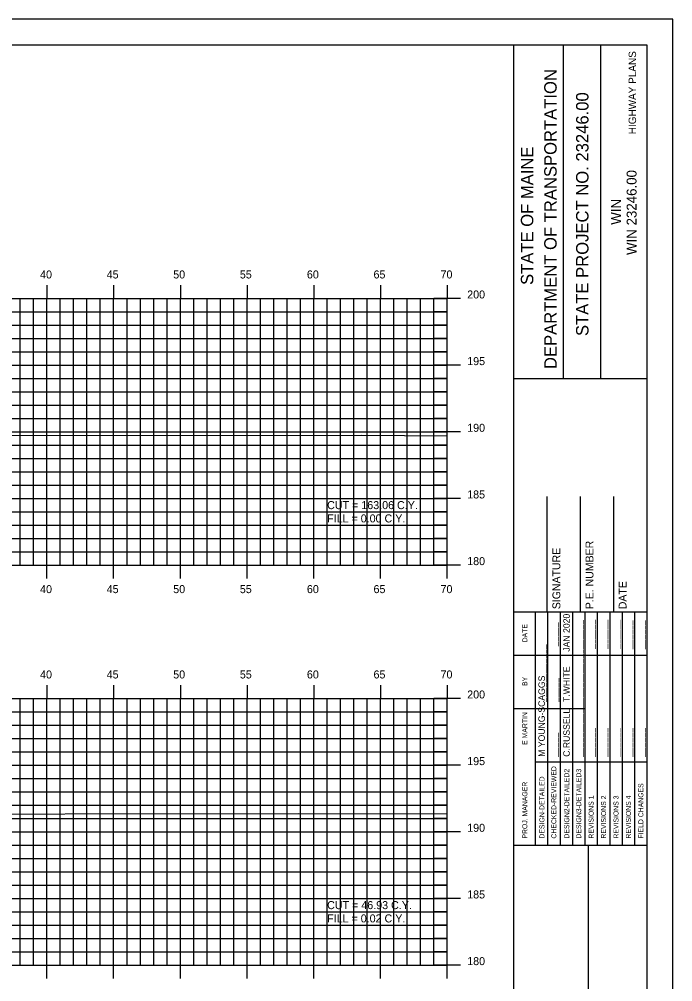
# Model space of a CAD drawing. Extents: x 1139207 to 1139377, y 608981 to 609091.
# Drawn here: x 1139327.6 to 1139376.6, y 609019.1 to 609091.3 of the extents above; entities that cross this region are included whole.
import ezdxf

# ---------------------------------------------------------------- set-up
doc = ezdxf.new("R2010")
doc.units = 0
for name, color, linetype in [('BORDER', 7, 'Continuous'), ('D_Text_Standard', 7, 'Continuous'), ('H_V ANNOTATION', 7, 'Continuous'), ('HIGHWAY_TITLE', 7, 'Continuous'), ('MAJOR', 7, 'Continuous'), ('MINOR', 7, 'Continuous'), ('PLOT BOUNDARY', 7, 'Continuous'), ('S_Roadway_Centerline', 7, 'Continuous')]:
    doc.layers.add(name, color=color, linetype=linetype)

msp = doc.modelspace()

# ---------------------------------------------------------------- linework, layer by layer
at = {"layer": 'BORDER'}
for p, q in [((1139364.705, 608984.335), (1139364.705, 609089.335)), ((1139368.434, 609064.332), (1139368.434, 609089.332)), ((1139371.229, 609064.332), (1139371.229, 609089.332)), ((1139364.706, 609064.329), (1139374.705, 609064.329)), ((1139367.205, 609046.838), (1139367.205, 609055.485)), ((1139369.705, 609046.838), (1139369.705, 609055.485)), ((1139372.205, 609046.838), (1139372.205, 609055.485)), ((1139364.705, 609046.838), (1139374.705, 609046.838)), ((1139364.705, 609029.338), (1139374.705, 609029.338)), ((1139370.296, 608994.338), (1139370.296, 609029.338))]:
    msp.add_line(p, q, dxfattribs=at)
msp.add_lwpolyline([(1139214.705, 608984.335), (1139374.705, 608984.335), (1139374.705, 609089.335), (1139214.705, 609089.335)], close=True, dxfattribs=at)
for points in [[(1139366.32, 609043.588), (1139366.32, 609046.838)], [(1139367.253, 609029.341), (1139367.253, 609046.838)], [(1139368.185, 609046.838), (1139368.185, 609029.341)], [(1139369.116, 609029.341), (1139369.116, 609046.838)], [(1139370.048, 609029.341), (1139370.048, 609046.838)], [(1139370.98, 609029.341), (1139370.98, 609046.838)], [(1139371.911, 609029.341), (1139371.911, 609046.838)], [(1139372.843, 609029.341), (1139372.843, 609046.838)], [(1139373.775, 609029.341), (1139373.775, 609046.838)], [(1139366.321, 609029.341), (1139366.321, 609046.132)], [(1139364.705, 609043.588), (1139374.705, 609043.588)], [(1139364.705, 609039.588), (1139366.321, 609039.588)], [(1139366.32, 609039.588), (1139370.047, 609039.588)], [(1139366.32, 609035.588), (1139374.705, 609035.588)]]:
    msp.add_lwpolyline(points, dxfattribs=at)
at = {"layer": 'MAJOR'}
for p, q in [((1139329.705, 609071.337), (1139329.705, 609070.335)), ((1139334.705, 609071.337), (1139334.705, 609070.335)), ((1139339.705, 609071.337), (1139339.705, 609070.335)), ((1139344.705, 609071.337), (1139344.705, 609070.335)), ((1139349.705, 609071.337), (1139349.705, 609070.335)), ((1139354.705, 609071.337), (1139354.705, 609070.335)), ((1139359.705, 609071.337), (1139359.705, 609070.335)), ((1139219.705, 609070.335), (1139359.705, 609070.335)), ((1139219.705, 609070.335), (1139359.705, 609070.335)), ((1139329.705, 609050.335), (1139329.705, 609070.335)), ((1139334.705, 609050.335), (1139334.705, 609070.335)), ((1139339.705, 609050.335), (1139339.705, 609070.335)), ((1139344.705, 609050.335), (1139344.705, 609070.335)), ((1139349.705, 609050.335), (1139349.705, 609070.335)), ((1139354.705, 609050.335), (1139354.705, 609070.335)), ((1139360.707, 609070.335), (1139358.703, 609070.335)), ((1139359.705, 609050.335), (1139359.705, 609070.335)), ((1139359.705, 609050.335), (1139359.705, 609070.335)), ((1139219.705, 609065.335), (1139359.705, 609065.335)), ((1139360.707, 609065.335), (1139358.703, 609065.335)), ((1139219.705, 609060.335), (1139359.705, 609060.335)), ((1139360.707, 609060.335), (1139358.703, 609060.335)), ((1139219.705, 609055.335), (1139359.705, 609055.335)), ((1139360.707, 609055.335), (1139358.703, 609055.335)), ((1139219.705, 609050.335), (1139359.705, 609050.335)), ((1139219.705, 609050.335), (1139359.705, 609050.335)), ((1139329.705, 609049.333), (1139329.705, 609050.335)), ((1139334.705, 609049.333), (1139334.705, 609050.335)), ((1139339.705, 609049.333), (1139339.705, 609050.335)), ((1139344.705, 609049.333), (1139344.705, 609050.335)), ((1139349.705, 609049.333), (1139349.705, 609050.335)), ((1139354.705, 609049.333), (1139354.705, 609050.335)), ((1139360.707, 609050.335), (1139358.703, 609050.335)), ((1139359.705, 609049.333), (1139359.705, 609050.335)), ((1139329.705, 609041.337), (1139329.705, 609040.335)), ((1139334.705, 609041.337), (1139334.705, 609040.335)), ((1139339.705, 609041.337), (1139339.705, 609040.335)), ((1139344.705, 609041.337), (1139344.705, 609040.335)), ((1139349.705, 609041.337), (1139349.705, 609040.335)), ((1139354.705, 609041.337), (1139354.705, 609040.335)), ((1139359.705, 609041.337), (1139359.705, 609040.335)), ((1139219.705, 609040.335), (1139359.705, 609040.335)), ((1139219.705, 609040.335), (1139359.705, 609040.335)), ((1139329.705, 609020.335), (1139329.705, 609040.335)), ((1139334.705, 609020.335), (1139334.705, 609040.335)), ((1139339.705, 609020.335), (1139339.705, 609040.335)), ((1139344.705, 609020.335), (1139344.705, 609040.335)), ((1139349.705, 609020.335), (1139349.705, 609040.335)), ((1139354.705, 609020.335), (1139354.705, 609040.335)), ((1139360.707, 609040.335), (1139358.703, 609040.335)), ((1139359.705, 609020.335), (1139359.705, 609040.335)), ((1139359.705, 609020.335), (1139359.705, 609040.335)), ((1139219.705, 609035.335), (1139359.705, 609035.335)), ((1139360.707, 609035.335), (1139358.703, 609035.335)), ((1139219.705, 609030.335), (1139359.705, 609030.335)), ((1139360.707, 609030.335), (1139358.703, 609030.335)), ((1139219.705, 609025.335), (1139359.705, 609025.335)), ((1139360.707, 609025.335), (1139358.703, 609025.335)), ((1139219.705, 609020.335), (1139359.705, 609020.335)), ((1139219.705, 609020.335), (1139359.705, 609020.335)), ((1139329.705, 609019.333), (1139329.705, 609020.335)), ((1139334.705, 609019.333), (1139334.705, 609020.335)), ((1139339.705, 609019.333), (1139339.705, 609020.335)), ((1139344.705, 609019.333), (1139344.705, 609020.335)), ((1139349.705, 609019.333), (1139349.705, 609020.335)), ((1139354.705, 609019.333), (1139354.705, 609020.335)), ((1139360.707, 609020.335), (1139358.703, 609020.335)), ((1139359.705, 609019.333), (1139359.705, 609020.335))]:
    msp.add_line(p, q, dxfattribs=at)
at = {"layer": 'MINOR'}
for p, q in [((1139327.705, 609050.335), (1139327.705, 609070.335)), ((1139328.705, 609050.335), (1139328.705, 609070.335)), ((1139330.705, 609050.335), (1139330.705, 609070.335)), ((1139331.705, 609050.335), (1139331.705, 609070.335)), ((1139332.705, 609050.335), (1139332.705, 609070.335)), ((1139333.705, 609050.335), (1139333.705, 609070.335)), ((1139335.705, 609050.335), (1139335.705, 609070.335)), ((1139336.705, 609050.335), (1139336.705, 609070.335)), ((1139337.705, 609050.335), (1139337.705, 609070.335)), ((1139338.705, 609050.335), (1139338.705, 609070.335)), ((1139340.705, 609050.335), (1139340.705, 609070.335)), ((1139341.705, 609050.335), (1139341.705, 609070.335)), ((1139342.705, 609050.335), (1139342.705, 609070.335)), ((1139343.705, 609050.335), (1139343.705, 609070.335)), ((1139345.705, 609050.335), (1139345.705, 609070.335)), ((1139346.705, 609050.335), (1139346.705, 609070.335)), ((1139347.705, 609050.335), (1139347.705, 609070.335)), ((1139348.705, 609050.335), (1139348.705, 609070.335)), ((1139350.705, 609050.335), (1139350.705, 609070.335)), ((1139351.705, 609050.335), (1139351.705, 609070.335)), ((1139352.705, 609050.335), (1139352.705, 609070.335)), ((1139353.705, 609050.335), (1139353.705, 609070.335)), ((1139355.705, 609050.335), (1139355.705, 609070.335)), ((1139356.705, 609050.335), (1139356.705, 609070.335)), ((1139357.705, 609050.335), (1139357.705, 609070.335)), ((1139358.705, 609050.335), (1139358.705, 609070.335)), ((1139219.705, 609069.335), (1139359.705, 609069.335)), ((1139359.705, 609069.335), (1139358.703, 609069.335)), ((1139219.705, 609068.335), (1139359.705, 609068.335)), ((1139359.705, 609068.335), (1139358.703, 609068.335)), ((1139219.705, 609067.335), (1139359.705, 609067.335)), ((1139359.705, 609067.335), (1139358.703, 609067.335)), ((1139219.705, 609066.335), (1139359.705, 609066.335)), ((1139359.705, 609066.335), (1139358.703, 609066.335)), ((1139219.705, 609064.335), (1139359.705, 609064.335)), ((1139359.705, 609064.335), (1139358.703, 609064.335)), ((1139219.705, 609063.335), (1139359.705, 609063.335)), ((1139359.705, 609063.335), (1139358.703, 609063.335)), ((1139219.705, 609062.335), (1139359.705, 609062.335)), ((1139359.705, 609062.335), (1139358.703, 609062.335)), ((1139219.705, 609061.335), (1139359.705, 609061.335)), ((1139359.705, 609061.335), (1139358.703, 609061.335)), ((1139219.705, 609059.335), (1139359.705, 609059.335)), ((1139359.705, 609059.335), (1139358.703, 609059.335)), ((1139219.705, 609058.335), (1139359.705, 609058.335)), ((1139359.705, 609058.335), (1139358.703, 609058.335)), ((1139219.705, 609057.335), (1139359.705, 609057.335)), ((1139359.705, 609057.335), (1139358.703, 609057.335)), ((1139219.705, 609056.335), (1139359.705, 609056.335)), ((1139359.705, 609056.335), (1139358.703, 609056.335)), ((1139219.705, 609054.335), (1139359.705, 609054.335)), ((1139359.705, 609054.335), (1139358.703, 609054.335)), ((1139219.705, 609053.335), (1139359.705, 609053.335)), ((1139359.705, 609053.335), (1139358.703, 609053.335)), ((1139219.705, 609052.335), (1139359.705, 609052.335)), ((1139359.705, 609052.335), (1139358.703, 609052.335)), ((1139219.705, 609051.335), (1139359.705, 609051.335)), ((1139359.705, 609051.335), (1139358.703, 609051.335)), ((1139327.705, 609020.335), (1139327.705, 609040.335)), ((1139328.705, 609020.335), (1139328.705, 609040.335)), ((1139330.705, 609020.335), (1139330.705, 609040.335)), ((1139331.705, 609020.335), (1139331.705, 609040.335)), ((1139332.705, 609020.335), (1139332.705, 609040.335)), ((1139333.705, 609020.335), (1139333.705, 609040.335)), ((1139335.705, 609020.335), (1139335.705, 609040.335)), ((1139336.705, 609020.335), (1139336.705, 609040.335)), ((1139337.705, 609020.335), (1139337.705, 609040.335)), ((1139338.705, 609020.335), (1139338.705, 609040.335)), ((1139340.705, 609020.335), (1139340.705, 609040.335)), ((1139341.705, 609020.335), (1139341.705, 609040.335)), ((1139342.705, 609020.335), (1139342.705, 609040.335)), ((1139343.705, 609020.335), (1139343.705, 609040.335)), ((1139345.705, 609020.335), (1139345.705, 609040.335)), ((1139346.705, 609020.335), (1139346.705, 609040.335)), ((1139347.705, 609020.335), (1139347.705, 609040.335)), ((1139348.705, 609020.335), (1139348.705, 609040.335)), ((1139350.705, 609020.335), (1139350.705, 609040.335)), ((1139351.705, 609020.335), (1139351.705, 609040.335)), ((1139352.705, 609020.335), (1139352.705, 609040.335)), ((1139353.705, 609020.335), (1139353.705, 609040.335)), ((1139355.705, 609020.335), (1139355.705, 609040.335)), ((1139356.705, 609020.335), (1139356.705, 609040.335)), ((1139357.705, 609020.335), (1139357.705, 609040.335)), ((1139358.705, 609020.335), (1139358.705, 609040.335)), ((1139219.705, 609039.335), (1139359.705, 609039.335)), ((1139359.705, 609039.335), (1139358.703, 609039.335)), ((1139219.705, 609038.335), (1139359.705, 609038.335)), ((1139359.705, 609038.335), (1139358.703, 609038.335)), ((1139219.705, 609037.335), (1139359.705, 609037.335)), ((1139359.705, 609037.335), (1139358.703, 609037.335)), ((1139219.705, 609036.335), (1139359.705, 609036.335)), ((1139359.705, 609036.335), (1139358.703, 609036.335)), ((1139219.705, 609034.335), (1139359.705, 609034.335)), ((1139359.705, 609034.335), (1139358.703, 609034.335)), ((1139219.705, 609033.335), (1139359.705, 609033.335)), ((1139359.705, 609033.335), (1139358.703, 609033.335)), ((1139219.705, 609032.335), (1139359.705, 609032.335)), ((1139359.705, 609032.335), (1139358.703, 609032.335)), ((1139219.705, 609031.335), (1139359.705, 609031.335)), ((1139359.705, 609031.335), (1139358.703, 609031.335)), ((1139219.705, 609029.335), (1139359.705, 609029.335)), ((1139359.705, 609029.335), (1139358.703, 609029.335)), ((1139219.705, 609028.335), (1139359.705, 609028.335)), ((1139359.705, 609028.335), (1139358.703, 609028.335)), ((1139219.705, 609027.335), (1139359.705, 609027.335)), ((1139359.705, 609027.335), (1139358.703, 609027.335)), ((1139219.705, 609026.335), (1139359.705, 609026.335)), ((1139359.705, 609026.335), (1139358.703, 609026.335)), ((1139219.705, 609024.335), (1139359.705, 609024.335)), ((1139359.705, 609024.335), (1139358.703, 609024.335)), ((1139219.705, 609023.335), (1139359.705, 609023.335)), ((1139359.705, 609023.335), (1139358.703, 609023.335)), ((1139219.705, 609022.335), (1139359.705, 609022.335)), ((1139359.705, 609022.335), (1139358.703, 609022.335)), ((1139219.705, 609021.335), (1139359.705, 609021.335)), ((1139359.705, 609021.335), (1139358.703, 609021.335))]:
    msp.add_line(p, q, dxfattribs=at)
at = {"layer": 'PLOT BOUNDARY'}
msp.add_lwpolyline([(1139206.612, 608981.276), (1139376.612, 608981.276), (1139376.612, 609091.276), (1139206.612, 609091.276)], close=True, dxfattribs=at)
at = {"layer": 'S_Roadway_Centerline'}
for points in [[(1139231.693, 609064.2), (1139235.188, 609064.142), (1139236.871, 609064.001), (1139239.489, 609063.871), (1139241.838, 609063.755), (1139250.238, 609063.378), (1139264.143, 609062.648), (1139264.256, 609062.641), (1139272.57, 609061.866), (1139275.873, 609061.633), (1139276.892, 609061.652), (1139282.291, 609061.733), (1139287.04, 609061.756), (1139292.681, 609061.794), (1139292.709, 609061.781), (1139297.486, 609061.69), (1139303.847, 609061.636), (1139305.717, 609061.239), (1139307.637, 609060.852), (1139309.089, 609060.674), (1139312.659, 609060.053), (1139353.311, 609060.081), (1139359.705, 609060.02)], [(1139268.743, 609032.962), (1139276.277, 609032.574), (1139276.277, 609032.574), (1139276.277, 609032.574), (1139278.743, 609032.693), (1139281.778, 609032.801), (1139285.759, 609032.805), (1139292.65, 609032.921), (1139292.728, 609033.025), (1139295.683, 609032.864), (1139303.307, 609032.796), (1139307.64, 609032.149), (1139307.746, 609032.136), (1139307.838, 609032.108), (1139308.052, 609032.088), (1139311.845, 609031.608), (1139313.562, 609031.651), (1139348.525, 609031.696), (1139359.705, 609031.676)]]:
    msp.add_lwpolyline(points, dxfattribs=at)

# ---------------------------------------------------------------- texts
at = {"layer": 'BORDER'}
for s, height, p in [('DEPARTMENT OF TRANSPORTATION', 0.93176, (1139367.912, 609065.041)), ('STATE PROJECT NO. 23246.00', 0.93176, (1139370.297, 609067.517)), ('STATE OF MAINE', 0.93176, (1139366.161, 609071.347)), ('WIN 23246.00', 0.74527, (1139373.901, 609073.596)), ('WIN', 0.7453, (1139372.742, 609075.865)), ('SIGNATURE', 0.5906, (1139368.186, 609047.03)), ('P.E. NUMBER', 0.59055, (1139370.666, 609047.03)), ('DATE', 0.5906, (1139373.147, 609047.03)), ('JAN 2020', 0.4845, (1139368.892, 609043.843)), ('DATE', 0.3714, (1139365.71, 609044.544)), ('_____', 0.4845, (1139367.923, 609044.243)), ('______', 0.4845, (1139369.786, 609044.063)), ('______', 0.4845, (1139370.718, 609044.065)), ('______', 0.4845, (1139371.65, 609044.067)), ('______', 0.4845, (1139372.581, 609044.067)), ('______', 0.4845, (1139373.513, 609044.036)), ('______', 0.4845, (1139374.445, 609044.036)), ('____________', 0.48455, (1139367.028, 609040.073)), ('____________', 0.48455, (1139369.786, 609040.073)), ('T.WHITE', 0.4845, (1139368.892, 609040.073)), ('BY', 0.3714, (1139365.71, 609041.273)), ('M YOUNG-SCAGGS', 0.48455, (1139367.028, 609035.961)), ('_____', 0.4845, (1139367.96, 609040.073)), ('____________', 0.48455, (1139369.786, 609035.961)), ('C.RUSSELL', 0.4845, (1139368.892, 609035.961)), ('E MARTIN', 0.3727, (1139365.71, 609036.855)), ('_____', 0.4845, (1139367.923, 609035.961)), ('______', 0.4845, (1139370.718, 609035.961)), ('______', 0.4845, (1139371.65, 609035.961)), ('______', 0.4845, (1139372.581, 609035.961)), ('______', 0.4845, (1139373.513, 609035.961)), ('______', 0.4845, (1139374.445, 609035.961)), ('CHECKED-REVIEWED', 0.37275, (1139367.886, 609029.826)), ('DESIGN2-DETAILED2', 0.37275, (1139368.855, 609029.826)), ('DESIGN3-DETAILED3', 0.37275, (1139369.75, 609029.826)), ('DESIGN-DETAILED', 0.37275, (1139366.992, 609029.826)), ('PROJ. MANAGER', 0.37275, (1139365.71, 609029.826)), ('FIELD CHANGES', 0.37275, (1139374.408, 609029.826)), ('REVISIONS 1', 0.37275, (1139370.681, 609029.826)), ('REVISIONS 2', 0.37275, (1139371.613, 609029.826)), ('REVISIONS 3', 0.37275, (1139372.545, 609029.826)), ('REVISIONS 4', 0.37275, (1139373.477, 609029.826))]:
    msp.add_text(s, height=height, rotation=90, dxfattribs=at).set_placement(p)
at = {"layer": 'D_Text_Standard'}
for s, p in [('CUT = 163.06 C.Y.', (1139350.705, 609054.535)), ('FILL = 0.00 C.Y.', (1139350.705, 609053.539)), ('CUT = 46.93 C.Y.', (1139350.705, 609024.535)), ('FILL = 0.02 C.Y.', (1139350.705, 609023.539))]:
    msp.add_text(s, height=0.6, dxfattribs=at).set_placement(p)
at = {"layer": 'H_V ANNOTATION'}
for s, p in [('40', (1139329.191, 609071.835)), ('45', (1139334.183, 609071.835)), ('50', (1139339.17, 609071.835)), ('55', (1139344.162, 609071.835)), ('60', (1139349.191, 609071.835)), ('65', (1139354.183, 609071.835)), ('70', (1139359.207, 609071.835)), ('200', (1139361.205, 609070.335)), ('195', (1139361.205, 609065.335)), ('190', (1139361.205, 609060.335)), ('185', (1139361.205, 609055.335)), ('180', (1139361.205, 609050.335)), ('40', (1139329.191, 609048.235)), ('45', (1139334.183, 609048.235)), ('50', (1139339.17, 609048.235)), ('55', (1139344.162, 609048.235)), ('60', (1139349.191, 609048.235)), ('65', (1139354.183, 609048.235)), ('70', (1139359.207, 609048.235)), ('40', (1139329.191, 609041.835)), ('45', (1139334.183, 609041.835)), ('50', (1139339.17, 609041.835)), ('55', (1139344.162, 609041.835)), ('60', (1139349.191, 609041.835)), ('65', (1139354.183, 609041.835)), ('70', (1139359.207, 609041.835)), ('200', (1139361.205, 609040.335)), ('195', (1139361.205, 609035.335)), ('190', (1139361.205, 609030.335)), ('185', (1139361.205, 609025.335)), ('180', (1139361.205, 609020.335))]:
    msp.add_text(s, height=0.6, dxfattribs=at).set_placement(p)
at = {"layer": 'HIGHWAY_TITLE'}
msp.add_text('HIGHWAY PLANS', height=0.55901, rotation=90, dxfattribs=at).set_placement((1139373.864, 609082.65))

doc.saveas('drawing.dxf')
